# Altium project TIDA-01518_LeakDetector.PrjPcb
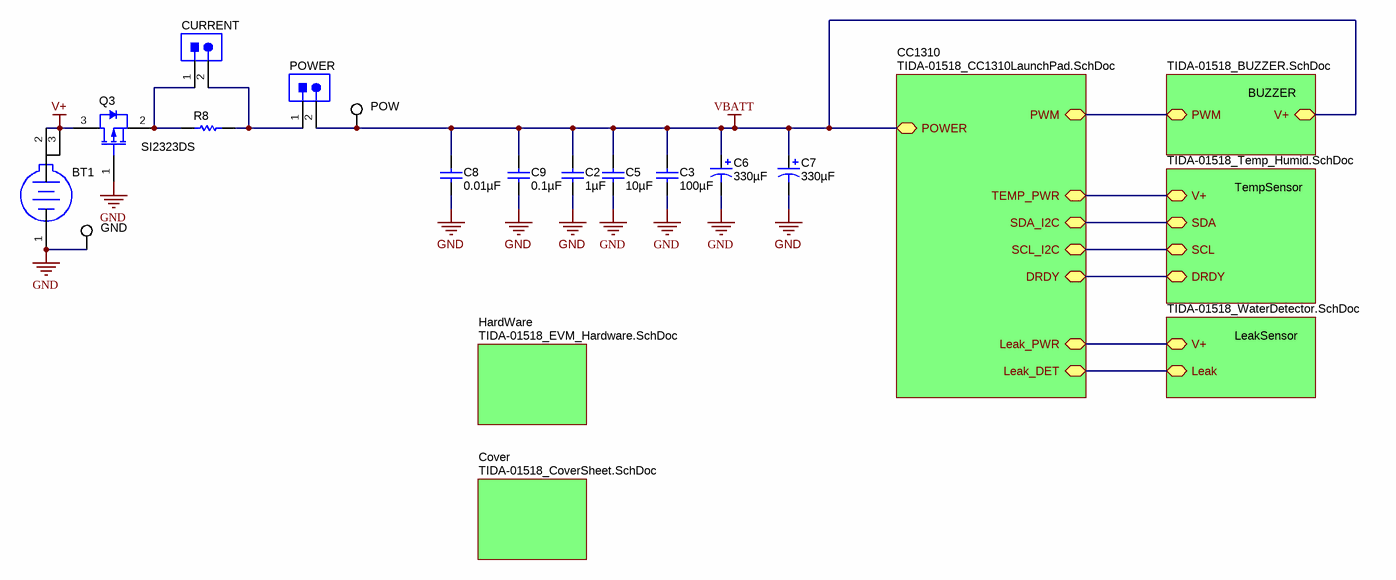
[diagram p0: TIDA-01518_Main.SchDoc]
TID: TIDA-01518; TechSupport: http://www.ti.com/support; SCH_Rev: A; PRJ_Title: Water Leak Detector; PRJ_Number: TIDA-01518; PRJ_Engineer: Dominic Cassaro; PRJ_Customer: Public Release; PCB_Rev: A; PCB_Layout: Dominic Cassaro; CopyrightYear: 2017
7 sheets, 54 parts. Net scope: hierarchical (ports join the sheet entries above them; power ports are global).
Board file: TIDA-01518_LeakDetector_PCB.PcbDoc
Sheets:
  TIDA-01518_Main.SchDoc
    TempSensor = TIDA-01518_Temp_Humid.SchDoc
    LeakSensor = TIDA-01518_WaterDetector.SchDoc
    CC1310 = TIDA-01518_CC1310LaunchPad.SchDoc
    BUZZER = TIDA-01518_BUZZER.SchDoc
    HardWare = TIDA-01518_EVM_Hardware.SchDoc
    Cover = TIDA-01518_CoverSheet.SchDoc

## Sheet TIDA-01518_Main.SchDoc
size 431 x 279 mm; Date: Not shown in title block; ApprovedBy: Not shown in title block; CheckedBy: Not shown in title block; Author: Not shown in title block; CompanyName: Not shown in title block; Engineer: Not shown in title block; Organization: Not shown in title block; Address1: Not shown in title block; Address2: Not shown in title block; Address3: Not shown in title block; Address4: Not shown in title block; DocumentNumber: 7; Revision: Use project parameter SCH_Rev; SheetNumber: 7; SheetTotal: 8; PageSetup: Record=PageOptions¦CenterHorizontal=True¦CenterVertical=True¦PrintScale=1.00¦XCorrection=1.00¦YCorrection=1.00¦PrintKind=0¦BorderSize=5000000¦LeftOffset=0¦BottomOffset=0¦Orientation=2¦PaperLength=1000¦PaperWidth=1000¦Scale=100¦PaperSource=15¦PrintQuality=600¦MediaType=1¦DitherType=10¦PaperKind=Letter¦PrintScaleMode=1

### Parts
BT1  BAT-HLD-001  [LINX_BAT-HLD-001]  (value not drawn)
C2  ValueDisplayed: 1µF  [0603]  (hidden comment: 06033C105KAT2A)
C3  ValueDisplayed: 100µF  [1206_190]  (hidden comment: C3216X5R1A107M160AC)
C5  ValueDisplayed: 10µF  [0805_HV]  (hidden comment: 0805YD106KAT2A)
C6  ValueDisplayed: 330µF  [6032-28]  (hidden comment: T495C337K004ATE700)
C7  ValueDisplayed: 330µF  [6032-28]  (hidden comment: T495C337K004ATE700)
C8  ValueDisplayed: 0.01µF  [0603]  (hidden comment: 06031C103JAT2A)
C9  ValueDisplayed: 0.1µF  [0805_HV]  (hidden comment: GCM21BR71H104KA37K)
CURRENT  61300211121  [WURTH_61300211121]  (value not drawn)
GND  5015  [Testpoint_Keystone_Miniature]  (value not drawn)
POW  5015  [Testpoint_Keystone_Miniature]  (value not drawn)
POWER  61300211121  [WURTH_61300211121]  (value not drawn)
Q3  SI2323DS  [SOT-23]
R8  CMF5010R200FHEB  [CMF50]  (value not drawn)

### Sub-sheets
BUZZER = TIDA-01518_BUZZER.SchDoc: PWM, V+
CC1310 = TIDA-01518_CC1310LaunchPad.SchDoc: POWER, SDA_I2C, SCL_I2C, DRDY, Leak_DET, PWM, TEMP_PWR, Leak_PWR
Cover = TIDA-01518_CoverSheet.SchDoc: no entries
HardWare = TIDA-01518_EVM_Hardware.SchDoc: no entries
LeakSensor = TIDA-01518_WaterDetector.SchDoc: Leak, V+
TempSensor = TIDA-01518_Temp_Humid.SchDoc: V+, SDA, SCL, DRDY

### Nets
GND: BT1.1(-) C2.2 C3.2 C5.2 C6.2(-) C7.2(-) C8.2 C9.2 GND.1 Q3.1(G)
V+: BT1.2(+) BT1.3(+) Q3.3(D)
VBATT: C2.1 C3.1 C5.1 C6.1(+) C7.1(+) C8.1 C9.1 POW.1 POWER.2 ; sheet CC1310/POWER, sheet BUZZER/V+  [project net 3v3]
A6/DIO 29: sheet TempSensor/V+, sheet CC1310/TEMP_PWR
DIO 12/ PWM1: sheet CC1310/PWM, sheet BUZZER/PWM
DIO 21: sheet TempSensor/DRDY, sheet CC1310/DRDY
DIO 22: sheet LeakSensor/Leak, sheet CC1310/Leak_DET
DIO 24/A1: sheet LeakSensor/V+, sheet CC1310/Leak_PWR
I2C SCL/ DIO 4: sheet TempSensor/SCL, sheet CC1310/SCL_I2C
I2C_SDA/DIO 5: sheet TempSensor/SDA, sheet CC1310/SDA_I2C
NetCURRENT_1: CURRENT.1 Q3.2(S) R8.1
NetCURRENT_2: CURRENT.2 POWER.1 R8.2

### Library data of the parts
BT1 = BAT-HLD-001: Battery Holder, Retainer clip, SMT; Manufacturer: Linx Technologies; SymbolCreator: a0411947
C2 = 06033C105KAT2A: CAP, CERM, 1 µF, 25 V,+/- 10%, X7R, 0603; Manufacturer: AVX; Polarized: N; CompType: Capacitor; Value: 1uF; U/M: EA; Cap_F: 0.000001; Tolerance_%: 10; VDC_V: 25; Value2: 25V; TaMin_C: -55; TaMax_C: 125; SizeArea_mm2: 1.28; SizeAreaWB_mm2: 4.68; SizeX_mm: 1.6; SizeY_mm: 0.8; SizeZ_mm: 1; AEC Category: Q200
C3 = C3216X5R1A107M160AC: CAP, CERM, 100 µF, 10 V, +/- 20%, X5R, 1206_190; Manufacturer: TDK; Polarized: N; CompType: Capacitor; Value: 100uF; U/M: EA; Cap_F: 0.0001; Tolerance_%: 20; Value1: Unknown; VDC_V: 10; Value2: 10V; TaMin_C: -55; TaMax_C: 85; Cap_Case: 1206
C5 = 0805YD106KAT2A: CAP, CERM, 10 µF, 16 V,+/- 10%, X5R, 0805; Manufacturer: AVX; Polarized: N; CompType: Capacitor; Value: 10uF; U/M: EA; Cap_F: 0.00001; Tolerance_%: 10; VDC_V: 16; Value2: 16V; TaMin_C: -55; TaMax_C: 85; Cap_Case: 0805; SizeArea_mm2: 2.5; SizeAreaWB_mm2: 6.75; SizeX_mm: 2; SizeY_mm: 1.25; SizeZ_mm: 1.45; AEC Category: Q200; Green_Lifecycle: Active; Green_REACh: Passed
C6 C7 = T495C337K004ATE700: CAP, TA, 330 µF, 4 V, +/- 10%, 0.7 ohm, SMD; Manufacturer: Kemet; Polarized: Y; CompType: Capacitor; Value: 330uF; U/M: EA; Cap_F: 0.00033; Tolerance_%: 10; Value1: 0.7 ohm; VDC_V: 4; Value2: 4V; ESR_ohm: 0.7; IRMS_A: 0.357; TaMin_C: -55; TaMax_C: 125; Cap_Case: C; SizeAreaWB_mm2: 41.6; SizeArea_mm2: 19.2; SizeX_mm: 6; SizeY_mm: 3.2; SizeZ_mm: 2.8; AEC Category: Q200
C8 = 06031C103JAT2A: CAP, CERM, 0.01 µF, 100 V,+/- 5%, X7R, 0603; Manufacturer: AVX; Polarized: N; CompType: Capacitor; Value: 0.01uF; U/M: EA; Cap_F: 0.00000001; Tolerance_%: 5; ESR_ohm: 0.098; Value1: 0.098 ohm; VDC_V: 100; Value2: 100V; TaMin_C: -55; TaMax_C: 125; SizeArea_mm2: 1.28; SizeAreaWB_mm2: 4.68; SizeX_mm: 1.6; SizeY_mm: 0.8; SizeZ_mm: 1; AEC Category: Q200; Green_Lifecycle: Active; Green_REACh: Passed
C9 = GCM21BR71H104KA37K: CAP, CERM, 0.1 µF, 50 V,+/- 10%, X7R, AEC-Q200 Grade 1, 0805; Manufacturer: MuRata; Polarized: N; CompType: Capacitor; Value: 0.1uF; U/M: EA; Cap_F: 0.0000001; Tolerance_%: 10; VDC_V: 50; Value2: 50V; TaMin_C: -55; TaMax_C: 125; Cap_Case: 0805; SizeArea_mm2: 2.5; SizeAreaWB_mm2: 6.75; SizeX_mm: 2; SizeY_mm: 1.25; SizeZ_mm: 1.45; AEC Category: Q200; AEC Qualified: Y; AEC Grade: 1
CURRENT POWER = 61300211121: Header, 2.54 mm, 2x1, Gold, TH; Manufacturer: Wurth Elektronik; SymbolCreator: a0412235; Green_Lifecycle: Active; Green_REACh: Passed
GND POW = 5015: Test Point, Miniature, SMT; Manufacturer: Keystone; CompType: Test Point Loop; U/M: EA
Q3 = SI2323DS: MOSFET, P-CH, -20 V, -3.7 A, SOT-23; Manufacturer: Vishay-Siliconix; Alternate Manufacturer: None; U/M: EA; ChType: P; Value: -20V; Value1: 0.031 ohm; Rdson45_ohm: 0.031; Value2: 12.5 nC; QgTyp_nC: 12.5; Vgs_V: -8; SizeAreaWB_mm2: 14; SizeArea_mm2: 7.5; SizeX_mm: 2.5; SizeY_mm: 3; SizeZ_mm: 1.1; AEC Category: Q101; Green_Lifecycle: Not Set; Green_REACh: Incomplete
R8 = CMF5010R200FHEB: RES, 10.2, 1%, 0.25 W, Axial; Manufacturer: Vishay-Dale; CompType: Resistor; Value: 10.2; Value_Code: 10R2; Tolerance_%: 1; Power_W: 0.25; Value2: 0.25W; VDC_V: 200; TempCo: 50 ppm/C; EIA_Code: E96; U/M: EA; AEC Category: Q200

## Sheet TIDA-01518_Temp_Humid.SchDoc
size 431 x 279 mm; Date: Not shown in title block; ApprovedBy: Not shown in title block; CheckedBy: Not shown in title block; Author: Not shown in title block; CompanyName: Not shown in title block; Engineer: Not shown in title block; Organization: Not shown in title block; Address1: Not shown in title block; Address2: Not shown in title block; Address3: Not shown in title block; Address4: Not shown in title block; DocumentNumber: 6; Revision: Use project parameter SCH_Rev; SheetNumber: 6; SheetTotal: 8; PageSetup: Record=PageOptions¦CenterHorizontal=True¦CenterVertical=True¦PrintScale=1.00¦XCorrection=1.00¦YCorrection=1.00¦PrintKind=0¦BorderSize=5000000¦LeftOffset=0¦BottomOffset=0¦Orientation=2¦PaperLength=1000¦PaperWidth=1000¦Scale=100¦PaperSource=15¦PrintQuality=600¦MediaType=1¦DitherType=10¦PaperKind=Letter¦PrintScaleMode=1
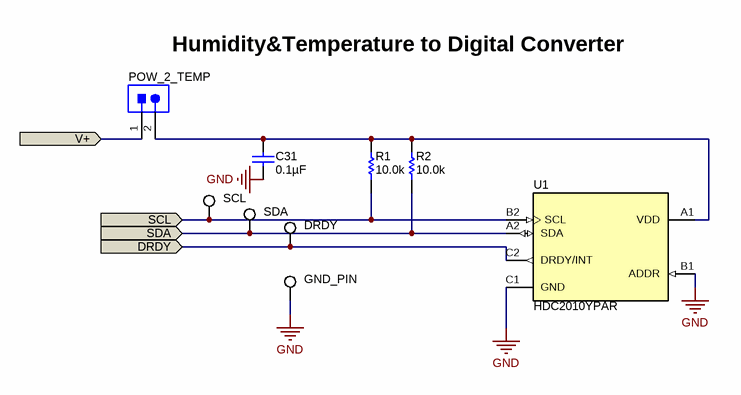
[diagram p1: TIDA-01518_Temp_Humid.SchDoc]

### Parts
C31  ValueDisplayed: 0.1µF  [0402L]  (hidden comment: GCM155R71H104KE02D)
DRDY  5015  [Testpoint_Keystone_Miniature]  (value not drawn)
GND_PIN  5015  [Testpoint_Keystone_Miniature]  (value not drawn)
POW_2_TEMP  61300211121  [WURTH_61300211121]  (value not drawn)
R1  ValueDisplayed: 10.0k  [0402]  (hidden comment: CRCW040210K0FKED)
R2  ValueDisplayed: 10.0k  [0402]  (hidden comment: CRCW040210K0FKED)
SCL  5015  [Testpoint_Keystone_Miniature]  (value not drawn)
SDA  5015  [Testpoint_Keystone_Miniature]  (value not drawn)
U1  HDC2010YPAR  [YPA0006ABAB]

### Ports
DRDY, SCL, SDA, V+

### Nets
GND: C31.2 GND_PIN.1 U1.B1(ADDR) U1.C1(GND)
A6/DIO 29: POW_2_TEMP.1 ; port V+
DIO 21: DRDY.1 U1.C2(DRDY/INT) ; port DRDY
I2C SCL/ DIO 4: R1.1 SCL.1 U1.B2(SCL) ; port SCL
I2C_SDA/DIO 5: R2.1 SDA.1 U1.A2(SDA) ; port SDA
NetC31_1: C31.1 POW_2_TEMP.2 R1.2 R2.2 U1.A1(VDD)

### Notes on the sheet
- Humidity&Temperature to Digital Converter

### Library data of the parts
C31 = GCM155R71H104KE02D: CAP, CERM, 0.1 µF, 50 V,+/- 10%, X7R, AEC-Q200 Grade 1, 0402; Manufacturer: MuRata; Polarized: N; CompType: Capacitor; Value: 0.1uF; U/M: EA; Cap_F: 0.0000001; Tolerance_%: 10; VDC_V: 50; Value2: 50V; TaMin_C: -55; TaMax_C: 125; Cap_Case: 0402; SizeArea_mm2: 0.5; SizeAreaWB_mm2: 3; SizeX_mm: 1; SizeZ_mm: 0.6; AEC Category: Q200; AEC Qualified: Y
DRDY GND_PIN SCL SDA = 5015: as GND on sheet TIDA-01518_Main
POW_2_TEMP = 61300211121: as CURRENT on sheet TIDA-01518_Main
R1 R2 = CRCW040210K0FKED: RES, 10.0 k, 1%, 0.063 W, 0402; Manufacturer: Vishay-Dale; CompType: Resistor; Value: 10.0k; Res_ohm: 10000; Value_Code: 10k0; Tolerance_%: 1; Power_W: 0.063; Value2: 0.063W; VDC_V: 50; TempCo: 100 ppm/C; EIA_Code: E96; U/M: EA
U1 = HDC2010YPAR: HDC2010 Low Power Humidity and Temperature Digital Sensor, YPA0006ABAB (DSBGA-6); Alternate PartNumber: HDC2010YPAT; Manufacturer: Texas Instruments; SymbolCreator: Altium; SizeArea_mm2: 2.1316; SizeAreaWB_mm2: 6.0516; SizeX_mm: 1.46; SizeZ_mm: 0.675; CompType: IC; U/M: EA

## Sheet TIDA-01518_WaterDetector.SchDoc
size 431 x 279 mm; Date: Not shown in title block; ApprovedBy: Not shown in title block; CheckedBy: Not shown in title block; Author: Not shown in title block; CompanyName: Not shown in title block; Engineer: Not shown in title block; Organization: Not shown in title block; Address1: Not shown in title block; Address2: Not shown in title block; Address3: Not shown in title block; Address4: Not shown in title block; DocumentNumber: 8; Revision: Use project parameter SCH_Rev; SheetNumber: 8; SheetTotal: 8; PageSetup: Record=PageOptions¦CenterHorizontal=True¦CenterVertical=True¦PrintScale=1.00¦XCorrection=1.00¦YCorrection=1.00¦PrintKind=0¦BorderSize=5000000¦LeftOffset=0¦BottomOffset=0¦Orientation=2¦PaperLength=1000¦PaperWidth=1000¦Scale=100¦PaperSource=15¦PrintQuality=600¦MediaType=1¦DitherType=10¦PaperKind=Letter¦PrintScaleMode=1
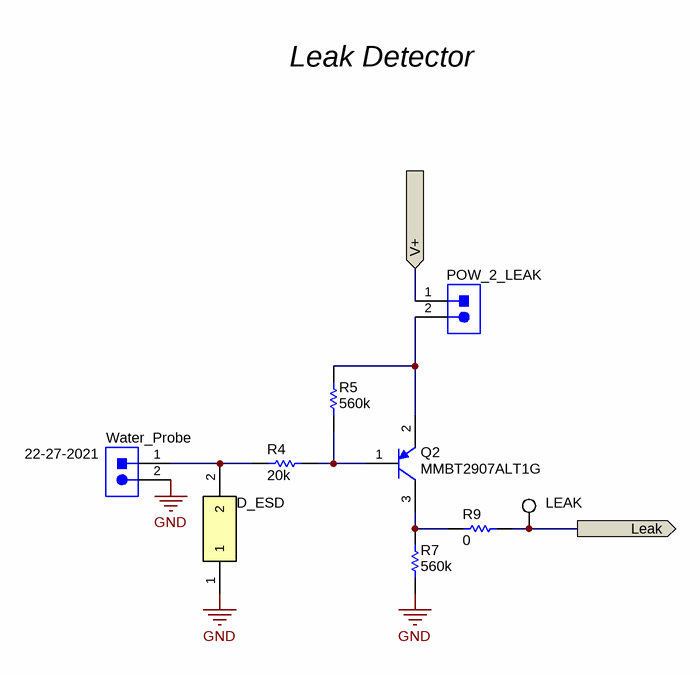
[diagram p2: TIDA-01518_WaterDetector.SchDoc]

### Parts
D_ESD  TPD1E10B06DPYR  [DPY0002A]  (value not drawn)
LEAK  5015  [Testpoint_Keystone_Miniature]  (value not drawn)
POW_2_LEAK  61300211121  [WURTH_61300211121]  (value not drawn)
Q2  MMBT2907ALT1G  [SOT-23]
R4  ValueDisplayed: 20k  [0603]  (hidden comment: CRCW060320K0JNEA)
R5  ValueDisplayed: 560k  [0603L]  (hidden comment: CRCW0603560KJNEA)
R7  ValueDisplayed: 560k  [0603L]  (hidden comment: CRCW0603560KJNEA)
R9  ValueDisplayed: 0  [0603]  (hidden comment: CRCW06030000Z0EA)
Water_Probe  22-27-2021  [MOLEX_22-27-2021]

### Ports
Leak, V+

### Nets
GND: D_ESD.1 R7.1 Water_Probe.2
DIO 22: LEAK.1 R9.2 ; port Leak
DIO 24/A1: POW_2_LEAK.1 ; port V+
NetD_ESD_2: D_ESD.2 R4.1 Water_Probe.1
NetPOW_2_LEAK_2: POW_2_LEAK.2 Q2.2(E) R5.2
NetQ2_1: Q2.1(B) R4.2 R5.1
NetQ2_3: Q2.3(C) R7.2 R9.1

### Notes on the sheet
- Leak Detector

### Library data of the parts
D_ESD = TPD1E10B06DPYR: ESD in 0402 Package with 10 pF Capacitance and 6 V Breakdown, 1 Channel, -40 to +125 degC, 2-pin X2SON (DPY), Green (RoHS & no Sb/Br); Manufacturer: Texas Instruments; Alternate PartNumber: Equivalent; Breakdown Voltage(Min)(V): 6; Eco-Plan: TBD; IEC 61000-4-2 Air-Gap(+/- kV): 30; IO Capacitance(Typ)(pF): 10; SubFamily: ESD Solution
LEAK = 5015: as GND on sheet TIDA-01518_Main
POW_2_LEAK = 61300211121: as CURRENT on sheet TIDA-01518_Main
Q2 = MMBT2907ALT1G, ON Semiconductor: Transistor, PNP, 60 V, 0.6 A, SOT-23; CompType: BJT; PNP: 1; NPN: 0; Vceo_V: 60; Vcesat1_V: 1.6; Value: 60 V; IcRated_A: 0.6; Value1: 0.6 A; TaMin_C: -55; TaMax_C: 150; SizeAreaWB_mm2: 14; SizeArea_mm2: 7.5; SizeX_mm: 2.5; SizeY_mm: 3; SizeZ_mm: 1.1; U/M: EA; AEC Category: Q101; Green_Lifecycle: Active; Green_REACh: Passed
R4 = CRCW060320K0JNEA: RES, 20 k, 5%, 0.1 W, 0603; Manufacturer: Vishay-Dale; CompType: Resistor; Value: 20k; Res_ohm: 20000; Value_Code: 20k0; Tolerance_%: 5; Power_W: 0.1; Value2: 0.1W; VDC_V: 75; TempCo: 200 ppm/C; SizeArea_mm2: 1.28; SizeX_mm: 1.6; SizeY_mm: 0.8; SizeZ_mm: 1; EIA_Code: E24; U/M: EA; AEC Category: Q200; Green_Lifecycle: Active; Green_REACh: Passed
R5 R7 = CRCW0603560KJNEA: RES, 560 k, 5%, 0.1 W, 0603; Manufacturer: Vishay-Dale; CompType: Resistor; Value: 560k; Res_ohm: 560000; Tolerance_%: 5; Power_W: 0.1; Value2: 0.1W; VDC_V: 75; TempCo: 200 ppm/C; SizeArea_mm2: 1.28; SizeX_mm: 1.6; SizeY_mm: 0.8; SizeZ_mm: 1; EIA_Code: E24; U/M: EA; AEC Category: Q200
R9 = CRCW06030000Z0EA: RES, 0, 5%, 0.1 W, 0603; Manufacturer: Vishay-Dale; CompType: Resistor; Value: 0; Value_Code: 0000; Tolerance_%: 5; Power_W: 0.1; Value2: 0.1W; VDC_V: 75; TempCo: 200 ppm/C; SizeArea_mm2: 1.28; SizeX_mm: 1.6; SizeY_mm: 0.8; SizeZ_mm: 1; EIA_Code: E24; U/M: EA; AEC Category: Q200; Green_Lifecycle: Active; Green_REACh: Passed
Water_Probe = 22-27-2021: Header (friction lock), 100mil, 2x1, Tin, TH; Manufacturer: Molex; SymbolCreator: a0412235

## Sheet TIDA-01518_CC1310LaunchPad.SchDoc
size 431 x 279 mm; Date: Not shown in title block; ApprovedBy: Not shown in title block; CheckedBy: Not shown in title block; Author: Not shown in title block; CompanyName: Not shown in title block; Engineer: Not shown in title block; Organization: Not shown in title block; Address1: Not shown in title block; Address2: Not shown in title block; Address3: Not shown in title block; Address4: Not shown in title block; DocumentNumber: 5; Revision: Use project parameter SCH_Rev; SheetNumber: 5; SheetTotal: 8; PageSetup: Record=PageOptions¦CenterHorizontal=True¦CenterVertical=True¦PrintScale=1.00¦XCorrection=1.00¦YCorrection=1.00¦PrintKind=0¦BorderSize=5000000¦LeftOffset=0¦BottomOffset=0¦Orientation=2¦PaperLength=1000¦PaperWidth=1000¦Scale=100¦PaperSource=15¦PrintQuality=600¦MediaType=1¦DitherType=10¦PaperKind=Letter¦PrintScaleMode=1
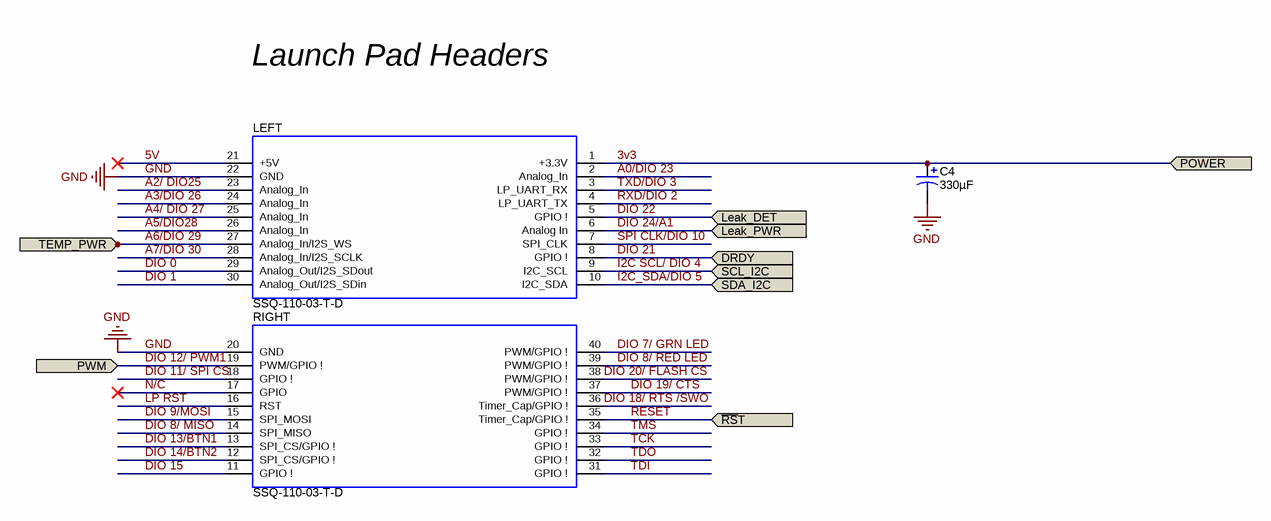
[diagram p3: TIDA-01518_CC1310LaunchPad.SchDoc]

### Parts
C4  ValueDisplayed: 330µF  [6032-28]  (hidden comment: T495C337K004ATE700)
LEFT  SSQ-110-03-T-D  [BoosterPack_40pin_J1J3]
RIGHT  SSQ-110-03-T-D  [BoosterPack_40pin_J2J4]

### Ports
DRDY, Leak_DET, Leak_PWR, POWER, PWM, SCL_I2C, SDA_I2C, TEMP_PWR, ~{RS}T

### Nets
3v3: C4.1(+) LEFT.1(+3.3V) ; port POWER
GND: C4.2(-) LEFT.22(GND) RIGHT.20(GND)
5V: LEFT.21(+5V)
A0/DIO 23: LEFT.2(Analog_In)
A2/ DIO25: LEFT.23(Analog_In)
A3/DIO 26: LEFT.24(Analog_In)
A4/ DIO 27: LEFT.25(Analog_In)
A5/DIO28: LEFT.26(Analog_In)
A6/DIO 29: LEFT.27(Analog_In/I2S_WS) ; port TEMP_PWR
A7/DIO 30: LEFT.28(Analog_In/I2S_SCLK)
DIO 0: LEFT.29(Analog_Out/I2S_SDout)
DIO 1: LEFT.30(Analog_Out/I2S_SDin)
DIO 7/ GRN LED: RIGHT.40(PWM/GPIO_!)
DIO 8/ MISO: RIGHT.14(SPI_MISO)
DIO 8/ RED LED: RIGHT.39(PWM/GPIO_!)
DIO 9/MOSI: RIGHT.15(SPI_MOSI)
DIO 11/ SPI CS: RIGHT.18(GPIO_!)
DIO 12/ PWM1: RIGHT.19(PWM/GPIO_!) ; port PWM
DIO 13/BTN1: RIGHT.13(SPI_CS/GPIO_!)
DIO 14/BTN2: RIGHT.12(SPI_CS/GPIO_!)
DIO 15: RIGHT.11(GPIO_!)
DIO 18/ RTS /SWO: RIGHT.36(Timer_Cap/GPIO_!)
DIO 19/ CTS: RIGHT.37(PWM/GPIO_!)
DIO 20/ FLASH CS: RIGHT.38(PWM/GPIO_!)
DIO 21: LEFT.8(GPIO_!) ; port DRDY
DIO 22: LEFT.5(GPIO_!) ; port Leak_DET
DIO 24/A1: LEFT.6(Analog_In) ; port Leak_PWR
I2C SCL/ DIO 4: LEFT.9(I2C_SCL) ; port SCL_I2C
I2C_SDA/DIO 5: LEFT.10(I2C_SDA) ; port SDA_I2C
LP RST: RIGHT.16(RST)
N/C: RIGHT.17(GPIO)
RESET: RIGHT.35(Timer_Cap/GPIO_!) ; port ~{RS}T
RXD/DIO 2: LEFT.4(LP_UART_TX)
SPI CLK/DIO 10: LEFT.7(SPI_CLK)
TCK: RIGHT.33(GPIO_!)
TDI: RIGHT.31(GPIO_!)
TDO: RIGHT.32(GPIO_!)
TMS: RIGHT.34(GPIO_!)
TXD/DIO 3: LEFT.3(LP_UART_RX)

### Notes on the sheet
- Launch Pad Headers

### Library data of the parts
C4 = T495C337K004ATE700: as C6 on sheet TIDA-01518_Main
LEFT = BoosterPack_40pin_J1J3: Receptacle, 2.54mm, 10x2, Tin, TH; Manufacturer: Samtec; Alternate Manufacturer: Major League Electronics; Alternate PartNumber: CRD-081413-A-G; SymbolCreator: a0412235; Note: Booster Pack 40 pin J1 and J3; Green_Lifecycle: Active; Green_REACh: Passed
RIGHT = BoosterPack_40pin_J2J4: Receptacle, 2.54mm, 10x2, Tin, TH; Manufacturer: Samtec; Alternate Manufacturer: Major League Electronics; Alternate PartNumber: CRD-081413-A-G; SymbolCreator: a0412235; Note: Booster Pack 40 pin J2 and J4; Green_Lifecycle: Active; Green_REACh: Passed

## Sheet TIDA-01518_BUZZER.SchDoc
size 431 x 279 mm; Date: Not shown in title block; ApprovedBy: Not shown in title block; CheckedBy: Not shown in title block; Author: Not shown in title block; CompanyName: Not shown in title block; Engineer: Not shown in title block; Organization: Not shown in title block; Address1: Not shown in title block; Address2: Not shown in title block; Address3: Not shown in title block; Address4: Not shown in title block; DocumentNumber: 4; Revision: Use project parameter SCH_Rev; SheetNumber: 4; SheetTotal: 8; PageSetup: Record=PageOptions¦CenterHorizontal=True¦CenterVertical=True¦PrintScale=1.00¦XCorrection=1.00¦YCorrection=1.00¦PrintKind=0¦BorderSize=5000000¦LeftOffset=0¦BottomOffset=0¦Orientation=2¦PaperLength=1000¦PaperWidth=1000¦Scale=100¦PaperSource=15¦PrintQuality=600¦MediaType=1¦DitherType=10¦PaperKind=Letter¦PrintScaleMode=1
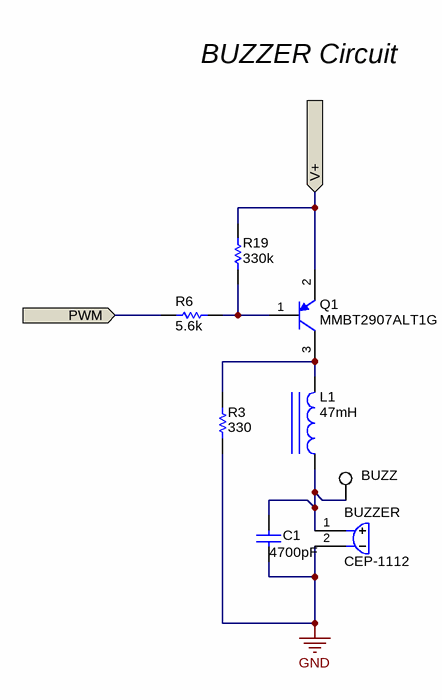
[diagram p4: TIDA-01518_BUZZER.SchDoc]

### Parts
BUZZ  5015  [Testpoint_Keystone_Miniature]  (value not drawn)
BUZZER  CEP-1112  [CUI_CEP-1112]
C1  ValueDisplayed: 4700pF  [0603]  (hidden comment: 06031C472JAT2A)
L1  Ind_H: 47mH  [RLB0913]  (hidden comment: RLB0913-473K)
Q1  MMBT2907ALT1G  [SOT-23]
R3  ValueDisplayed: 330  [1206]  (hidden comment: CRCW1206330RJNEA)
R6  ValueDisplayed: 5.6k  [0603]  (hidden comment: CRCW06035K60JNEA)
R19  ValueDisplayed: 330k  [0402L]  (hidden comment: CRCW0402330KJNED)

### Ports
PWM, V+

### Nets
3v3: Q1.2(E) R19.2 ; port V+
GND: BUZZER.2(-) C1.2 R3.1
DIO 12/ PWM1: R6.1 ; port PWM
NetBUZZ_1: BUZZ.1 BUZZER.1(+) C1.1 L1.1
NetL1_2: L1.2 Q1.3(C) R3.2
NetQ1_1: Q1.1(B) R6.2 R19.1

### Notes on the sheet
- BUZZER Circuit

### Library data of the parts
BUZZ = 5015: as GND on sheet TIDA-01518_Main
BUZZER = CMP-0077105-1: Piezo Audio Transducer, TH; Manufacturer: CUI Inc.; SizeAreaWB_mm2: 676.0; SizeArea_mm2: 576.0; SizeZ_mm: 7.3; SizeY_mm: 24.0; CompType: Buzzer
C1 = 06031C472JAT2A: CAP, CERM, 4700 pF, 100 V,+/- 5%, X7R, 0603; Manufacturer: AVX; Polarized: N; CompType: Capacitor; Value: 4700pF; U/M: EA; Cap_F: 0.0000000047; Tolerance_%: 5; ESR_ohm: 0.136; Value1: 0.136 ohm; VDC_V: 100; Value2: 100V; TaMin_C: -55; TaMax_C: 125; SizeArea_mm2: 1.28; SizeAreaWB_mm2: 4.68; SizeX_mm: 1.6; SizeY_mm: 0.8; SizeZ_mm: 1; AEC Category: Q200; Green_Lifecycle: Active; Green_REACh: Passed
L1 = CMP-0077104-1: Inductor, Wirewound, Ferrite, 47 mH, .03 A, 99 ohm, TH; Manufacturer: Bourns; SizeAreaWB_mm2: 110.25; Irms: 0.055A @ 40C rise; SizeArea_mm2: 72.25; AEC Qualified: N; AEC Category: Q200; Value: 47mH; SizeZ_mm: 12.5; Imax_A: 30mA; SizeY_mm: 8.5; Value2: .03A; Isat: .03A @ 10% inductance drop; Value1: 99 ohm; DCR_ohm: 99
Q1 = MMBT2907ALT1G, ON Semiconductor: as Q2 on sheet TIDA-01518_WaterDetector
R3 = CRCW1206330RJNEA: RES, 330, 5%, 0.25 W, 1206; Manufacturer: Vishay-Dale; CompType: Resistor; Value: 330; Value_Code: 330R; Tolerance_%: 5; Power_W: 0.25; Value2: 0.25W; VDC_V: 200; TempCo: 200 ppm/C; SizeArea_mm2: 5.12; SizeX_mm: 3.2; SizeY_mm: 1.6; SizeZ_mm: 1.35; EIA_Code: E24; U/M: EA; AEC Category: Q200
R6 = CRCW06035K60JNEA: RES, 5.6 k, 5%, 0.1 W, 0603; Manufacturer: Vishay-Dale; CompType: Resistor; Value: 5.6k; Res_ohm: 5600; Value_Code: 5k60; Tolerance_%: 5; Power_W: 0.1; Value2: 0.1W; VDC_V: 75; TempCo: 200 ppm/C; SizeArea_mm2: 1.28; SizeX_mm: 1.6; SizeY_mm: 0.8; SizeZ_mm: 1; EIA_Code: E24; U/M: EA; AEC Category: Q200; Green_Lifecycle: Active; Green_REACh: Passed
R19 = CRCW0402330KJNED: RES, 330 k, 5%, 0.063 W, 0402; Manufacturer: Vishay-Dale; CompType: Resistor; Value: 330k; Res_ohm: 330000; Tolerance_%: 5; Power_W: 0.063; Value2: 0.063W; VDC_V: 50; TempCo: 200 ppm/C; SizeArea_mm2: 0.5; SizeX_mm: 1; SizeZ_mm: 0.6; EIA_Code: E24; U/M: EA; AEC Category: Q200; Green_Lifecycle: Active; Green_REACh: Passed

## Sheet TIDA-01518_EVM_Hardware.SchDoc
size 431 x 279 mm; Date: Not shown in title block; ApprovedBy: Not shown in title block; CheckedBy: Not shown in title block; Author: Not shown in title block; CompanyName: Not shown in title block; Engineer: Not shown in title block; Organization: Not shown in title block; Address1: Not shown in title block; Address2: Not shown in title block; Address3: Not shown in title block; Address4: Not shown in title block; DocumentNumber: 3; Revision: Use project parameter SCH_Rev; SheetNumber: 3; SheetTotal: 8; PageSetup: Record=PageOptions¦CenterHorizontal=True¦CenterVertical=True¦PrintScale=1.00¦XCorrection=1.00¦YCorrection=1.00¦PrintKind=0¦BorderSize=5000000¦LeftOffset=0¦BottomOffset=0¦Orientation=2¦PaperLength=1000¦PaperWidth=1000¦Scale=100¦PaperSource=15¦PrintQuality=600¦MediaType=1¦DitherType=10¦PaperKind=Letter¦PrintScaleMode=1
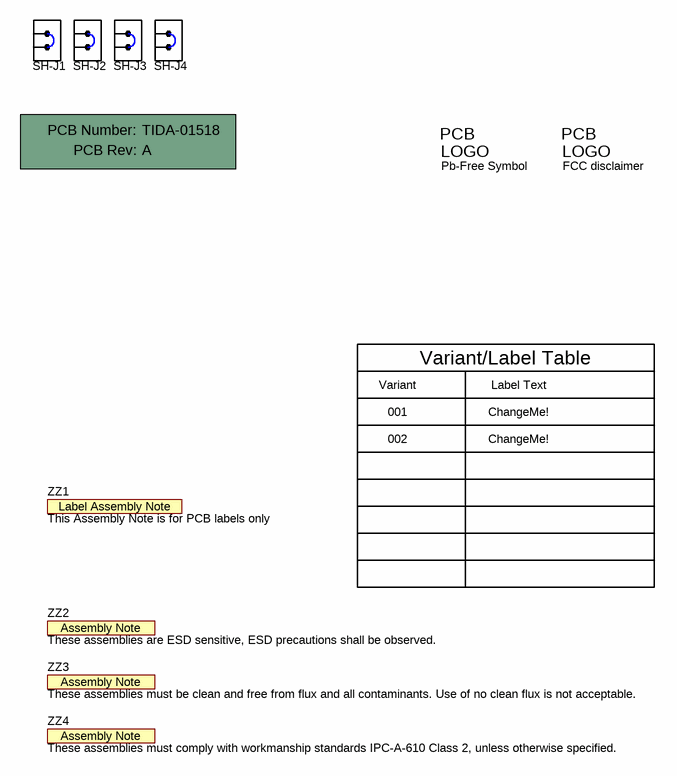
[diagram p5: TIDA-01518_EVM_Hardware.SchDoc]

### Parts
!PCB  Printed Circuit Board  (value not drawn)  (mechanical)
Logo2  Pb-Free Symbol  [Pb-Free_Overlay_Small]  (no BOM)
Logo3  FCC disclaimer  [FCC_disclaimer]  (no BOM)
SH-J1  2SN-BK-G  [2SN-BK-G]  (value not drawn)
SH-J2  2SN-BK-G  [2SN-BK-G]  (value not drawn)
SH-J3  2SN-BK-G  [2SN-BK-G]  (value not drawn)
SH-J4  2SN-BK-G  [2SN-BK-G]  (value not drawn)
ZZ1  This Assembly Note is for PCB labels only  [AssemblyNoteLabel]  (no BOM)
ZZ2  These assemblies are ESD sensitive, ESD precautions shall be observed.  [AssemblyNote]  (no BOM)
ZZ3  These assemblies must be clean and free from flux and all contaminants. Use of no clean flux is not acceptable.  [AssemblyNote]  (no BOM)
ZZ4  These assemblies must comply with workmanship standards IPC-A-610 Class 2, unless otherwise specified.  [AssemblyNote]  (no BOM)

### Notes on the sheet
- Variant
- Variant/Label Table
- Label Text
- 001
- 002
- ChangeMe!

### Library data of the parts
!PCB = PCB: Manufacturer: Any; PartNumber: TIDA-01518; SymbolCreator: a0412235
Logo2 = Pb-Free: SymbolCreator: a0412235
Logo3 = FCC_disclaimer: SymbolCreator: codlsc
SH-J1-SH-J4 = 2SN-BK-G: Shunt, 2mm, Gold plated, Black; Manufacturer: Samtec; Value: 1x2; Note: You can "mate" this to a header by matching the designator.  i.e. use SH-J3 for header J3; Green_Lifecycle: Active; Green_REACh: Passed
ZZ1 = AssemblyNoteLabel: SymbolCreator: a0412235
ZZ2-ZZ4 = AssemblyNote: SymbolCreator: codlsc

## Sheet TIDA-01518_CoverSheet.SchDoc
size 431 x 279 mm; Date: Not shown in title block; ApprovedBy: Not shown in title block; CheckedBy: Not shown in title block; Author: Not shown in title block; CompanyName: Not shown in title block; Engineer: Not shown in title block; Organization: Not shown in title block; Address1: Not shown in title block; Address2: Not shown in title block; Address3: Not shown in title block; Address4: Not shown in title block; DocumentNumber: 1; Revision: Use project parameter SCH_Rev; SheetNumber: 1; SheetTotal: 8; PageSetup: Record=PageOptions¦CenterHorizontal=True¦CenterVertical=True¦PrintScale=1.00¦XCorrection=1.00¦YCorrection=1.00¦PrintKind=0¦BorderSize=5000000¦LeftOffset=0¦BottomOffset=0¦Orientation=2¦PaperLength=1000¦PaperWidth=1000¦Scale=100¦PaperSource=15¦PrintQuality=600¦MediaType=1¦DitherType=10¦PaperKind=Letter¦PrintScaleMode=1
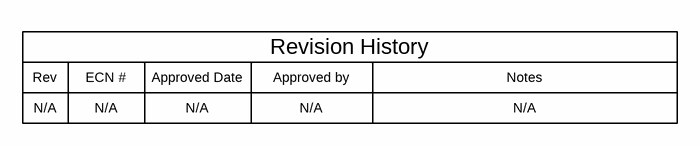
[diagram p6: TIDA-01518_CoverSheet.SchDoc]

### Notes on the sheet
- Rev
- N/A
- ECN #
- Approved Date
- Approved by
- Revision History
- Notes

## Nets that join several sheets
3v3: TIDA-01518_Main (9 pins), TIDA-01518_CC1310LaunchPad (C4.1 LEFT.1), TIDA-01518_BUZZER (Q1.2 R19.2)
GND: TIDA-01518_Main (10 pins), TIDA-01518_Temp_Humid (C31.2 GND_PIN.1 U1.B1 U1.C1), TIDA-01518_WaterDetector (D_ESD.1 R7.1 Water_Probe.2), TIDA-01518_CC1310LaunchPad (C4.2 LEFT.22 RIGHT.20), TIDA-01518_BUZZER (BUZZER.2 C1.2 R3.1)
A6/DIO 29: TIDA-01518_Temp_Humid (POW_2_TEMP.1), TIDA-01518_CC1310LaunchPad (LEFT.27)
DIO 12/ PWM1: TIDA-01518_CC1310LaunchPad (RIGHT.19), TIDA-01518_BUZZER (R6.1)
DIO 21: TIDA-01518_Temp_Humid (DRDY.1 U1.C2), TIDA-01518_CC1310LaunchPad (LEFT.8)
DIO 22: TIDA-01518_WaterDetector (LEAK.1 R9.2), TIDA-01518_CC1310LaunchPad (LEFT.5)
DIO 24/A1: TIDA-01518_WaterDetector (POW_2_LEAK.1), TIDA-01518_CC1310LaunchPad (LEFT.6)
I2C SCL/ DIO 4: TIDA-01518_Temp_Humid (R1.1 SCL.1 U1.B2), TIDA-01518_CC1310LaunchPad (LEFT.9)
I2C_SDA/DIO 5: TIDA-01518_Temp_Humid (R2.1 SDA.1 U1.A2), TIDA-01518_CC1310LaunchPad (LEFT.10)

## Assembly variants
001: all parts fitted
